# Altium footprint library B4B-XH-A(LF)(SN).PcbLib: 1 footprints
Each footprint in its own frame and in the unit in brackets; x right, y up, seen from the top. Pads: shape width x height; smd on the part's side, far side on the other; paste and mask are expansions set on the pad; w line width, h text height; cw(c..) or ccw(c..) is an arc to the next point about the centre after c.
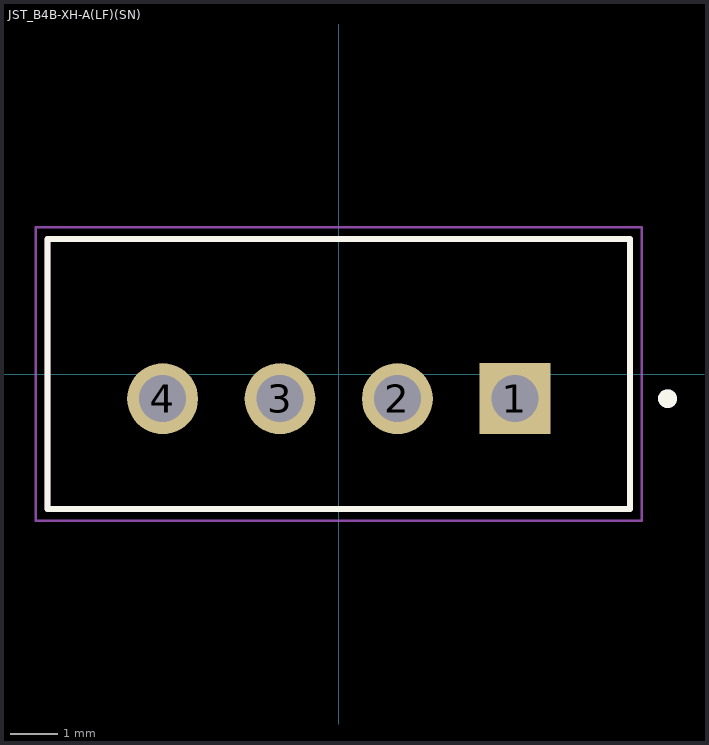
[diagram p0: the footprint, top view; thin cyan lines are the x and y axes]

## JST_B4B-XH-A(LF)(SN) [mm]
height 7
pads (4):
  rect 1.508x1.508 / inner round 1.508 / far side rect 1.508x1.508 hole 1: 1(3.75,-0.525)
  round 1.508 hole 1: 2(1.25,-0.525) 3(-1.25,-0.525) 4(-3.75,-0.525)
Top Overlay:
  circle w0.2: c7,-0.525 r0.1
  lines w0.127: -6.2,-2.875 -6.2,2.875 6.2,2.875 6.2,-2.875 -6.2,-2.875
Mechanical 13:
  circle w0.2: c7,-0.525 r0.1
  lines w0.127: -6.2,-2.875 -6.2,2.875 6.2,2.875 6.2,-2.875 -6.2,-2.875
Mechanical 15:
  lines w0.05: -6.45,-3.125 -6.45,3.125 6.45,3.125 6.45,-3.125 -6.45,-3.125
3D body "step_temp.STEP": height 7, standoff -3.4, extent -6.2,-2.875 6.2,2.875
